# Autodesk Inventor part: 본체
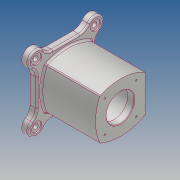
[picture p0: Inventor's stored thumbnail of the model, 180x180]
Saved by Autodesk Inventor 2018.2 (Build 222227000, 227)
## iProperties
Created: 2022-01
Part Number: 본체
Material: 알루미늄 6061
Document SubType Name: Modeling
Designer: woori
Density: 2.7 g/cm^3
Appearance: 알루미늄 - 평지
Mass: 1225.02 g
Surface Area: 908.487 cm^2
Volume: 453.711 cm^3
Author: woori
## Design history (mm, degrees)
sketch "스케치1"
  geometry: L1 (-53, 53)-(53, 53); L2 (53, 53)-(53, -53); L3 (53, -53)-(-53, -53); L4 (-53, -53)-(-53, 53); L5 (-53, 53)-(53, -53); L6 (53, 53)-(-53, -53); A1 r 15 centre (53, 53) between (53, 38) and (38, 53); A2 r 15 centre (53, -53) between (38, -53) and (53, -38); A3 r 15 centre (-53, -53) between (-53, -38) and (-38, -53); A4 r 15 centre (-53, 53) between (-38, 53) and (-53, 38); 1 further point
  constraints: 12 end point, 8 point on circle, 8 point on line, 4 centre point, 4 coincident, 2 midpoint, 2 parallel, 1 horizontal, 1 perpendicular
  dimensions: "d0" = 106 distance between parallel lines of L3 L1; "d1" = 106 distance of L2.end L3.end; "d3" = 30 diameter of A1; "d4" = 30 diameter of A2; "d5" = 30 diameter of A3; "d6" = 30 diameter of A4
extrude "돌출1" new body sketch "스케치1" distance "d7" = 12; taper "d8" = 0 deg
node "작업 평면1"
sketch "스케치7"
  geometry: L1 (-45, 45)-(45, 45); L2 (45, 45)-(45, -45); L3 (45, -45)-(-45, -45); L4 (-45, -45)-(-45, 45); L5 (-45, 45)-(45, -45); L6 (45, 45)-(-45, -45); A1 r 90 centre (45, 0) between (-32.942, 45) and (-32.942, -45); A2 r 90 centre (0, -45) between (45, 32.942) and (-45, 32.942); A3 r 90 centre (0, 45) between (-45, -32.942) and (45, -32.942); 1 further point
  constraints: 12 end point, 8 point on circle, 6 point on line, 5 midpoint, 3 centre point, 2 parallel, 1 horizontal, 1 perpendicular, 1 tangent
  dimensions: "d30" = 90 distance of L2.end L3.end; "d31" = 90 distance of L1.end L2.end; "d32" = 180 diameter of A2
extrude "돌출5" join sketch "스케치7" distance "d33" = 98; taper "d34" = 0 deg
sketch "스케치8"
  geometry: L1 (-32.942, 45)-(32.942, 45) reference; L2 (129.574, -96.698)-(-129.574, -96.698); L3 (-129.574, -96.698)-(-129.574, 186.698); L4 (-129.574, 186.698)-(129.574, 186.698); L5 (129.574, 186.698)-(129.574, -96.698); L6 (129.574, -96.698)-(-129.574, 186.698); L7 (-129.574, -96.698)-(129.574, 186.698); C1 r 90 at (0, 45); 1 further point
  constraints: 12 end point, 3 midpoint, 2 parallel, 1 centre point, 1 horizontal, 1 perpendicular
  dimensions: "d35" = 180 diameter of C1; "d36" = 283.39565 distance between parallel lines of L2 L4; "d37" = 259.14864 distance between parallel lines of L3 L5
extrude "돌출6" cut sketch "스케치8" distance "d38" = 98; taper "d39" = 0 deg
sketch "스케치9"
  geometry: L1 (110, -37.029)-(110, 45) reference; L2 (110, 0)-(110, 25); L3 (110, 25)-(98, 25); L4 (12, 45)-(12, -37.029) reference; L5 (110, 0)-(0, 0); L6 (98, 25)-(98, 37); L7 (98, 37)-(12, 37); L8 (12, 37)-(12, 25); L9 (0, 25)-(0, 0); L10 (0, 38)-(0, -38) reference; L11 (12, 25)-(0, 25)
  constraints: 16 end point, 3 point on line, 2 horizontal, 2 perpendicular, 1 collinear, 1 vertical
  dimensions: "d40" = 25 distance of L2.start L2.end; "d47" = 12 distance of L2.end L3.end; "d48" = 37 distance between parallel lines of L5 L7; "d49" = 86 distance of L6.end L7.end; "d50" = 25 distance between parallel lines of L5 L11
revolve "회전2" sketch "스케치9" stored, may be unused: angle "d51" = 90 deg
sketch "스케치10"
  geometry: L1 (0, 65.885)-(0, 0) reference; L2 (-110, 70.942)-(-110, -5.058) reference; C1 r 20 at (-49, 32.942); 2 further points
  constraints: 1 centre point, 1 horizontal alignment, 1 midpoint
  dimensions: "d52" = 40 diameter of C1; "d53" = 61 distance from line of C1.centre L2
extrude "돌출7" join sketch "스케치10" distance "d54" = 10; taper "d55" = 0 deg
feature "면 기울기1" dims angle "d56" = 10 deg
sketch "스케치11"
  geometry: C1 r 20 at (0, 0) reference; C2 r 12 at (0, 0); 1 further point
  constraints: 1 centre point, 1 coincident
  dimensions: "d58" = 24 diameter of C2
extrude "돌출8" cut sketch "스케치11" distance "d59" = 30; taper "d60" = 0 deg
node "작업 평면2"
sketch "스케치12"
  geometry: C1 r 12 at (0, 0) reference; C2 r 15 at (0, 0); 1 further point
  constraints: 1 centre point, 1 coincident
  dimensions: "d62" = 30 diameter of C2
extrude "돌출9" cut sketch "스케치12" distance "d63" = 30; taper "d64" = 0 deg
sketch "스케치13" dims "d65" = 80
  geometry: L1 (53, -53)-(-53, 53); A1 r 15 centre (53, -53) between (38, -53) and (53, -38) reference; A2 r 15 centre (-53, 53) between (-38, 53) and (-53, 38) reference; A3 r 15 centre (-53, -53) between (-53, -38) and (-38, -53) reference; A4 r 15 centre (53, 53) between (53, 38) and (38, 53) reference; 3 further points
  constraints: 2 end point, 1 coincident, 1 point on line, 3 other
hole "구멍1" sketch "스케치13" at (-28.284, 28.284) diameter "d66" = 3.242; stored, may be unused: countersink angle "d70" = 90 deg, drill point angle "d72" = 118 deg; dims "d67" = 9, "d68" = 4, "d69" = 2, "d71" = 11
fillet "모깎기1" dims "d76" = 20
sketch "스케치14" dims "d77" = 80
  geometry: L1 (53, 53)-(-53, -53); A1 r 15 centre (53, 53) between (61.571, 40.69) and (40.69, 61.571) reference; A2 r 15 centre (-53, -53) between (-61.571, -40.69) and (-40.69, -61.571) reference; 3 further points
  constraints: 2 end point, 1 coincident, 1 point on line, 3 other
hole "구멍2" sketch "스케치14" at (28.284, 28.284) diameter "d78" = 3.242; stored, may be unused: countersink angle "d82" = 90 deg, drill point angle "d84" = 118 deg; dims "d79" = 9, "d80" = 4, "d81" = 2, "d83" = 11
sketch "스케치16" dims "d89" = 150
  geometry: L1 (53, 53)-(-53, -53); A1 r 15 centre (53, 53) between (61.571, 40.69) and (40.69, 61.571) reference; A2 r 15 centre (-53, -53) between (-61.571, -40.69) and (-40.69, -61.571) reference; 3 further points
  constraints: 2 end point, 1 coincident, 1 point on line, 3 other
hole "구멍3" sketch "스케치16" at (53.033, 53.033) diameter "d90" = 9; stored, may be unused: countersink angle "d94" = 90 deg, drill point angle "d96" = 118 deg; dims "d91" = 9, "d92" = 18, "d93" = 2, "d95" = 11
node "작업 평면3"
sketch "스케치17"
  geometry: L1 (-94.777, 29.147)-(-27.223, 29.147); L2 (-27.223, 29.147)-(-27.223, -29.147); L3 (-27.223, -29.147)-(-94.777, -29.147); L4 (-94.777, -29.147)-(-94.777, 29.147); L5 (-27.223, -29.147)-(-94.777, -29.147); L6 (-94.777, -29.147)-(-94.777, 29.147); L7 (-94.777, 29.147)-(-27.223, 29.147); L8 (-27.223, 29.147)-(-27.223, -29.147); L9 (-27.223, -29.147)-(-94.777, 29.147); L10 (-94.777, -29.147)-(-27.223, 29.147); L11 (-41, 55)-(-81, 55) reference; L12 (0, 68)-(0, 40.69) reference; 3 further points
  constraints: 12 end point, 2 coincident, 2 midpoint, 2 parallel, 1 horizontal, 1 perpendicular, 2 other
  dimensions: "d101" = 55 distance from line of point (-61, 0) L11; "d102" = 61 distance from line of L12 point (-61, 0)
extrude "돌출10" join sketch "스케치17" stored distance "d103" = 30; taper "d104" = 0 deg
fillet "모깎기2" dims "d105" = 1
fillet "모깎기3" dims "d106" = 3
fillet "모깎기4" dims "d107" = 3
fillet "모깎기5" dims "d108" = 3
node "솔리드1"
pattern_circular "원형 패턴1" dims angle "d74" = 360 deg
pattern_circular "원형 패턴2" dims angle "d86" = 360 deg
pattern_circular "원형 패턴3" dims angle "d98" = 360 deg
other parameters: "d61" = -13, "d100" = -45.5
